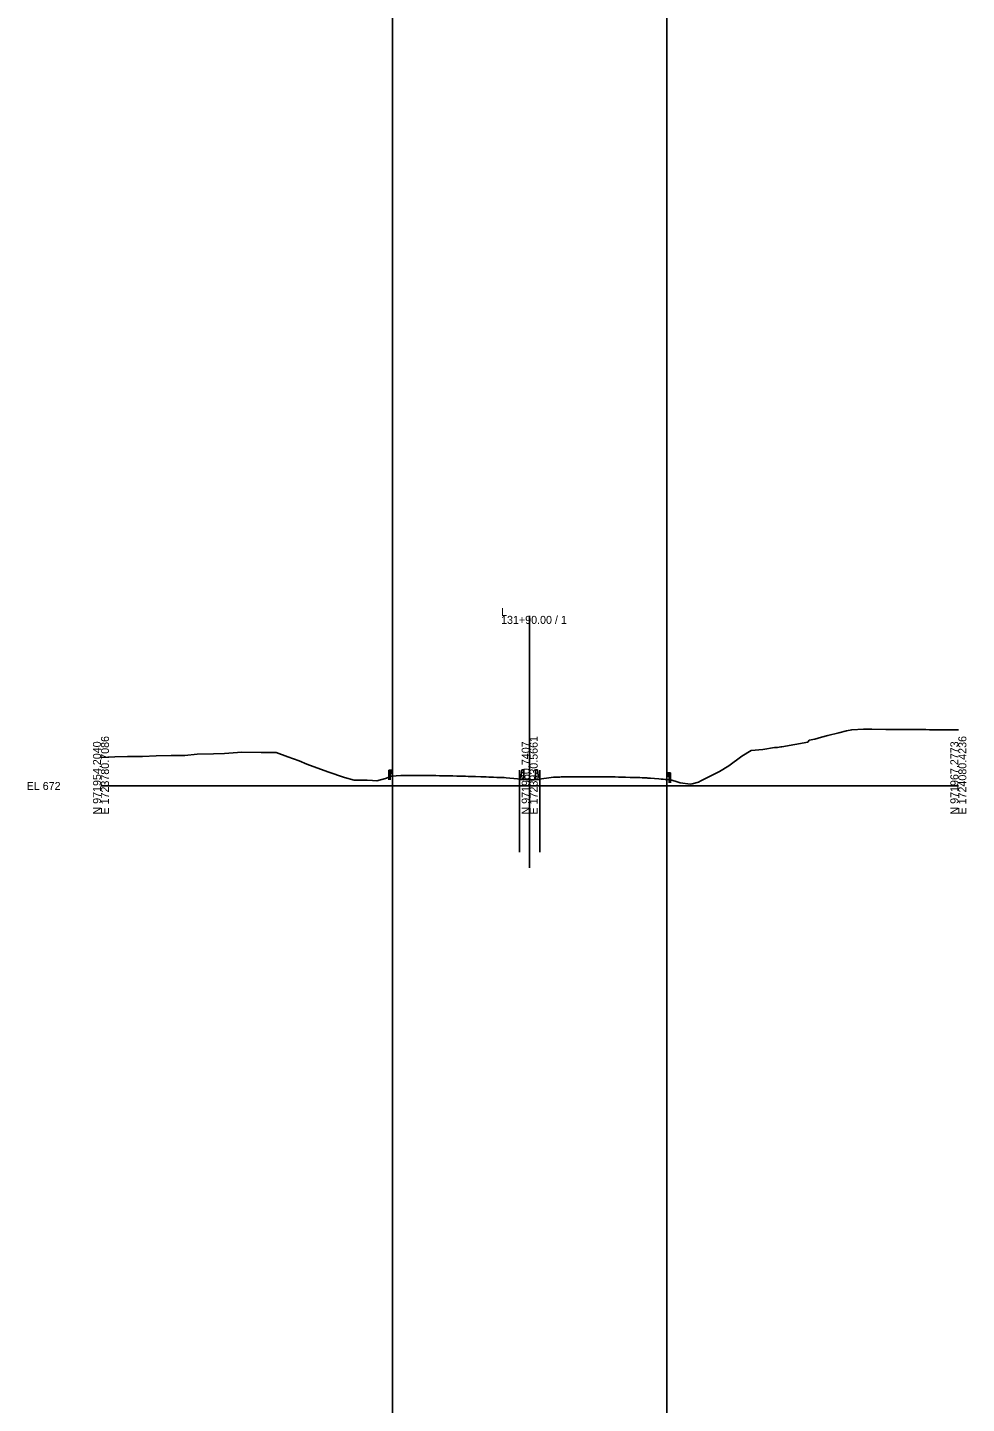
# Model space of a CAD drawing. Extents: x -26 to 303, y -29 to 15026.
# Drawn here: x -25.7 to 302.8, y 8283.9 to 8765.4 of the extents above; entities that cross this region are included whole.
import ezdxf

# ---------------------------------------------------------------- set-up
doc = ezdxf.new("R2010")
doc.units = 0
for name, color, linetype in [('Exist Cross Section Cell', 7, 'Continuous'), ('Exist XS Center Line Elevation Label', 7, 'Continuous'), ('Exist XS Ground Line', 7, 'Continuous'), ('Scratch_Level_0', 7, 'Continuous'), ('Typical Guardrail CELL', 7, 'Continuous'), ('Typical Median Barrier CELL', 7, 'Continuous')]:
    doc.layers.add(name, color=color, linetype=linetype)

msp = doc.modelspace()

# ---------------------------------------------------------------- linework, layer by layer
at = {"layer": 'Exist Cross Section Cell'}
for p, q in [((150, 8500), (150, 8559.53)), ((0, 8500), (150, 8500)), ((150, 8500), (300, 8500))]:
    msp.add_line(p, q, dxfattribs=at)
at = {"layer": 'Exist XS Ground Line'}
msp.add_lwpolyline([(0, 8510.01), (4.89, 8510.15), (9.31, 8510.3), (14.48, 8510.37), (19.32, 8510.51), (24.6, 8510.66), (29.33, 8510.68), (33.66, 8511.13), (39.34, 8511.25), (43.25, 8511.4), (49.35, 8511.8), (56.09, 8511.7), (61.28, 8511.73), (65.37, 8510.16), (69.37, 8508.77), (72.02, 8507.6), (79.38, 8504.9), (85.23, 8502.98), (88.58, 8502.03), (91.6, 8502.04), (93.12, 8502.02), (94.96, 8501.93), (96.47, 8501.83), (99.56, 8502.65), (101.61, 8503.46), (104.91, 8503.62), (105.45, 8503.67), (106.14, 8503.71), (107.79, 8503.71), (108.49, 8503.71), (110.14, 8503.7), (111.35, 8503.7), (112.18, 8503.68), (113.51, 8503.66), (114.57, 8503.65), (116.02, 8503.63), (117.18, 8503.61), (118.51, 8503.6), (119.72, 8503.57), (121, 8503.54), (122.23, 8503.51), (123.08, 8503.5), (124.47, 8503.46), (125.99, 8503.41), (127.61, 8503.38), (128.48, 8503.36), (130.24, 8503.3), (131, 8503.27), (132.86, 8503.21), (133.5, 8503.19), (134.74, 8503.14), (135.71, 8503.1), (137.3, 8503.05), (138.54, 8503.01), (141.12, 8502.92), (141.82, 8502.9), (145.79, 8502.53), (147.81, 8502.35), (150, 8502.14), (150.6, 8502.08), (151.55, 8502.17), (156.74, 8502.83), (158.4, 8503.04), (158.87, 8503.07), (160.51, 8503.12), (161.03, 8503.14), (162.87, 8503.18), (163.54, 8503.2), (163.88, 8503.21), (164.31, 8503.23), (165.17, 8503.23), (166.08, 8503.23), (167.68, 8503.24), (168.56, 8503.24), (169.51, 8503.24), (171.07, 8503.25), (172.5, 8503.24), (173.57, 8503.24), (174.73, 8503.24), (176.07, 8503.23), (177.16, 8503.21), (177.51, 8503.2), (178.56, 8503.18), (179.94, 8503.14), (181.05, 8503.11), (182.57, 8503.08), (183.54, 8503.06), (185.16, 8503.01), (186.05, 8502.98), (187.81, 8502.93), (188.55, 8502.91), (189.37, 8502.89), (191.05, 8502.8), (191.4, 8502.78), (191.93, 8502.75), (192.34, 8502.73), (193.65, 8502.6), (195.22, 8502.45), (196.05, 8502.4), (196.72, 8502.36), (197.39, 8502.31), (197.98, 8502.25), (199.37, 8502.1), (201.99, 8501.35), (202.67, 8501.14), (206.32, 8500.67), (206.83, 8500.78), (209.12, 8501.35), (209.89, 8501.8), (216.46, 8505.06), (219.7, 8507.08), (224.23, 8510.48), (227.52, 8512.36), (231.53, 8512.79), (235.67, 8513.43), (236.72, 8513.48), (237.92, 8513.74), (238.19, 8513.67), (247.31, 8515.34), (247.8, 8516), (249.76, 8516.41), (252.15, 8517.11), (254.35, 8517.7), (258.23, 8518.58), (260.86, 8519.27), (262.68, 8519.68), (266.77, 8519.84), (269.73, 8519.84), (274.63, 8519.81), (279.32, 8519.8), (280.09, 8519.8), (282.02, 8519.8), (283.53, 8519.78), (285.29, 8519.77), (285.67, 8519.76), (286.88, 8519.74), (288.24, 8519.73), (288.66, 8519.73), (289.86, 8519.7), (291.16, 8519.7), (292.48, 8519.69), (293.67, 8519.68), (295.1, 8519.67), (296.17, 8519.66), (297.74, 8519.64), (298.68, 8519.62), (299.56, 8519.6), (300, 8519.59)], dxfattribs=at)
at = {"layer": 'Scratch_Level_0'}
for p, q in [((102, 15009.56), (102, -28.7)), ((198, 15009.56), (198, -28.7)), ((146.46, 8505.5), (146.46, 8476.8)), ((153.54, 8505.5), (153.54, 8476.8)), ((150, 8500), (150, 8471.3)), ((150, 8500), (150, 8471.3))]:
    msp.add_line(p, q, dxfattribs=at)
at = {"layer": 'Typical Guardrail CELL'}
for p, q in [((101.18, 8505.58), (100.68, 8505.58)), ((100.68, 8505.58), (100.68, 8503.09)), ((101.18, 8505.58), (101.18, 8503.09)), ((101.18, 8505.58), (101.68, 8505.58)), ((101.18, 8504.42), (101.68, 8504.42)), ((101.68, 8505.58), (101.68, 8504.42)), ((101.68, 8505.58), (101.97, 8505.38)), ((101.68, 8505.05), (101.97, 8505.25)), ((101.68, 8505), (101.68, 8505.05)), ((101.68, 8505), (101.68, 8504.95)), ((101.68, 8504.95), (101.97, 8504.75)), ((101.68, 8504.42), (101.97, 8504.62)), ((198.32, 8504.59), (198.03, 8504.38)), ((198.82, 8504.59), (198.32, 8504.59)), ((198.32, 8504.59), (198.32, 8503.43)), ((198.82, 8504.59), (198.82, 8502.1)), ((198.82, 8504.59), (199.32, 8504.59)), ((199.32, 8504.59), (199.32, 8502.1)), ((101.18, 8503.09), (100.68, 8503.09)), ((100.68, 8503.09), (100.68, 8502.09)), ((101.18, 8503.09), (101.18, 8502.09)), ((198.32, 8504.05), (198.03, 8504.26)), ((198.32, 8503.96), (198.03, 8503.76)), ((198.32, 8503.43), (198.03, 8503.63)), ((198.32, 8504.01), (198.32, 8504.05)), ((198.32, 8504.01), (198.32, 8503.96)), ((198.82, 8503.43), (198.32, 8503.43)), ((198.82, 8502.1), (199.32, 8502.1)), ((198.82, 8502.1), (198.82, 8501.09)), ((199.32, 8502.1), (199.32, 8501.09))]:
    msp.add_line(p, q, dxfattribs=at)
for centre, start, end in [((101.92, 8505.31), 304.9888, 54.997), ((101.92, 8504.69), 304.9634, 54.9941), ((198.08, 8504.32), 125.003, 235.0112), ((198.08, 8503.69), 125.0059, 235.0366)]:
    msp.add_arc(centre, 0.0776, start, end, dxfattribs=at)
at = {"layer": 'Typical Median Barrier CELL'}
for p, q in [((147.07, 8503.71), (147.29, 8505.67)), ((147.29, 8505.67), (147.96, 8505.67)), ((147.96, 8505.67), (147.96, 8502.25)), ((152.71, 8505.67), (152.04, 8505.67)), ((152.04, 8505.67), (152.04, 8502.25)), ((152.93, 8503.71), (152.71, 8505.67)), ((146.46, 8502.67), (146.92, 8503.32)), ((146.46, 8502.25), (146.46, 8502.67)), ((147.96, 8502.25), (146.46, 8502.25)), ((152.04, 8502.25), (153.54, 8502.25)), ((153.54, 8502.67), (153.08, 8503.32)), ((153.54, 8502.25), (153.54, 8502.67))]:
    msp.add_line(p, q, dxfattribs=at)
for centre, start, end in [((146.24, 8503.8), 325.0039, 353.9447), ((153.76, 8503.8), 186.0553, 214.9961)]:
    msp.add_arc(centre, 0.833, start, end, dxfattribs=at)

# ---------------------------------------------------------------- texts
at = {"layer": 'Exist Cross Section Cell'}
for s, p in [('L', (140, 8559.53)), ('131+90.00 / 1', (140, 8556.73)), ('EL 672', (-26, 8498.6))]:
    msp.add_text(s, height=2.8, dxfattribs=at).set_placement(p)
for s, p in [('N 971954.2040', (0, 8490)), ('E 1723780.7086', (2.8, 8490)), ('N 971960.7407', (150, 8490)), ('E 1723930.5661', (152.8, 8490)), ('N 971967.2773', (300, 8490)), ('E 1724080.4236', (302.8, 8490))]:
    msp.add_text(s, height=2.8, rotation=90, dxfattribs=at).set_placement(p)
at = {"layer": 'Exist XS Center Line Elevation Label'}
msp.add_text('674.14', height=0.18, dxfattribs=at).set_placement((149.64, 8501.65))

doc.saveas('drawing.dxf')
